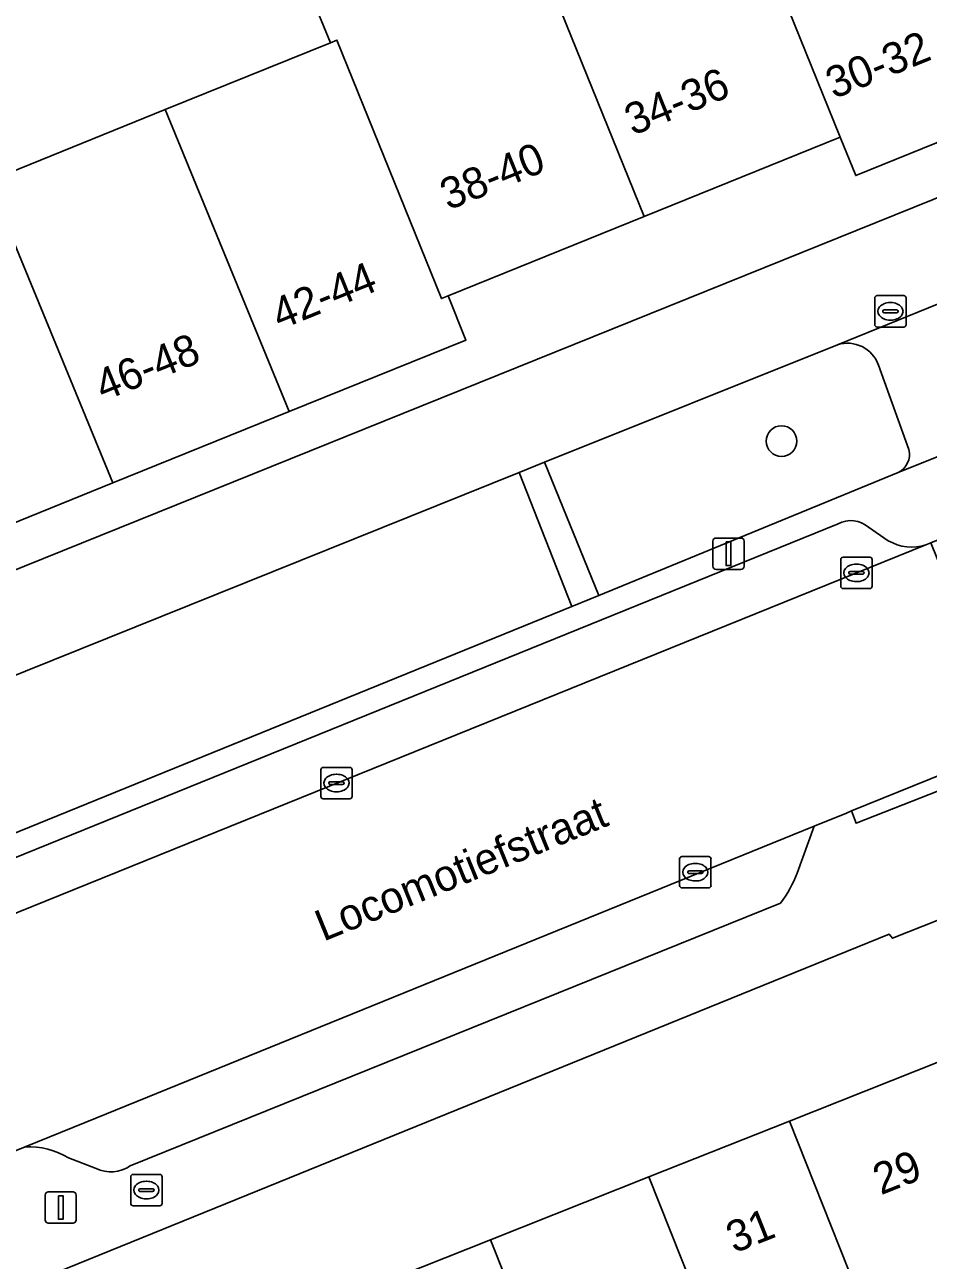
# Model space of a CAD drawing. Extents: x 162989 to 165008, y 383432 to 384338.
# Drawn here: x 163873.96 to 163902.79, y 383958.35 to 383997.76 of the extents above; entities that cross this region are included whole.
import ezdxf

# ---------------------------------------------------------------- set-up
doc = ezdxf.new("R2010")
doc.units = 0
for name, color, linetype in [('IMGEO_Boom', 7, 'Continuous'), ('IMGEO_Brandkraan', 7, 'Continuous'), ('IMGEO_Erf', 7, 'Continuous'), ('IMGEO_Groenvoorziening', 7, 'Continuous'), ('IMGEO_Kolk', 7, 'Continuous'), ('IMGEO_Lichtmast', 7, 'Continuous'), ('IMGEO_Openbare_ruimte_label', 7, 'Continuous'), ('IMGEO_Pand', 7, 'Continuous'), ('IMGEO_Pand_nummerreeks', 7, 'Continuous'), ('IMGEO_Parkeervlak_open', 7, 'Continuous'), ('IMGEO_Rijbaan_lokaal_open', 7, 'Continuous'), ('IMGEO_Rioolput', 7, 'Continuous'), ('IMGEO_Voetpad_open', 7, 'Continuous')]:
    doc.layers.add(name, color=color, linetype=linetype)

msp = doc.modelspace()

# ---------------------------------------------------------------- linework, layer by layer
at = {"layer": 'IMGEO_Boom'}
msp.add_circle((163898.104, 383984.479), 0.489, dxfattribs=at)
at = {"layer": 'IMGEO_Brandkraan'}
for p, q in [((163877.342, 383960.162), (163877.342, 383961.014)), ((163877.417, 383961.088), (163878.269, 383961.088)), ((163878.343, 383961.014), (163878.343, 383960.162)), ((163877.601, 383960.582), (163877.601, 383960.594)), ((163877.644, 383960.631), (163878.042, 383960.631)), ((163877.83, 383960.868), (163877.855, 383960.868)), ((163878.085, 383960.594), (163878.085, 383960.582)), ((163878.039, 383960.545), (163877.641, 383960.545)), ((163877.853, 383960.308), (163877.828, 383960.308)), ((163878.269, 383960.088), (163877.417, 383960.088))]:
    msp.add_line(p, q, dxfattribs=at)
for points in [[(163877.342, 383960.162), (163877.342, 383961.014)], [(163877.417, 383961.088), (163878.269, 383961.088)], [(163878.343, 383961.014), (163878.343, 383960.162)], [(163878.269, 383960.088), (163877.417, 383960.088)]]:
    msp.add_lwpolyline(points, dxfattribs=at)
for centre, radius, start, end in [((163877.419, 383961.012), 0.0765, 91.552, 178.448), ((163877.419, 383961.012), 0.0765, 91.552, 178.448), ((163878.267, 383961.012), 0.0765, 1.552, 88.448), ((163878.267, 383961.012), 0.0765, 1.552, 88.448), ((163877.641, 383960.591), 0.0403, 85.8775, 175.7526), ((163877.638, 383960.581), 0.0366, 178.938, 274.7102), ((163878.042, 383960.588), 0.043, 264.8664, 352.4533), ((163878.046, 383960.593), 0.0386, 1.7309, 96.639), ((163877.419, 383960.164), 0.0765, 181.552, 268.448), ((163877.419, 383960.164), 0.0765, 181.552, 268.448), ((163878.267, 383960.164), 0.0765, 271.552, 358.448), ((163878.267, 383960.164), 0.0765, 271.552, 358.448)]:
    msp.add_arc(centre, radius, start, end, dxfattribs=at)
for centre, major_axis, ratio, start_param, end_param in [((163877.829, 383960.588), (-0.387, 0.002), 0.722429, 4.712389, 7.853982), ((163877.854, 383960.588), (-0.39, 0.002), 0.717154, 1.570796, 4.712389)]:
    msp.add_ellipse(centre, major_axis=major_axis, ratio=ratio, start_param=start_param, end_param=end_param, dxfattribs=at)
at = {"layer": 'IMGEO_Erf'}
for points in [[(163860.657, 383975.132), (163922.286, 384000), (163935.54, 384005.348), (163935.283, 384006.035), (163927.294, 384027.344)], [(163863.146, 383998.341), (163858.852, 383996.609), (163861.551, 383988.223), (163867.173, 383990.498), (163872.805, 383992.776), (163878.436, 383995.055), (163883.712, 383997.189), (163883.071, 383998.773)], [(163906.07, 383995.217), (163900.474, 383992.948), (163899.978, 383994.175), (163893.721, 383991.644), (163887.464, 383989.112), (163888.034, 383987.703), (163882.402, 383985.424), (163876.771, 383983.146), (163871.139, 383980.867), (163865.501, 383978.586), (163865.079, 383979.629), (163857.441, 383976.539)], [(163952.554, 383989.112), (163941.789, 383984.802), (163918.144, 383975.149), (163901.64, 383968.618), (163901.539, 383968.747), (163868.264, 383955.232)], [(163883.709, 383956.971), (163888.821, 383959.002), (163893.876, 383961.01), (163898.355, 383962.789), (163903.224, 383964.723), (163905.069, 383960.077), (163907.655, 383953.567)]]:
    msp.add_lwpolyline(points, dxfattribs=at)
at = {"layer": 'IMGEO_Groenvoorziening'}
for points in [[(163899.886, 383987.554), (163890.546, 383983.807), (163892.281, 383979.552), (163901.827, 383983.48)], [(163902.163, 383984.207), (163901.197, 383986.903)]]:
    msp.add_lwpolyline(points, dxfattribs=at)
msp.add_lwpolyline([(163872.224, 383971.398), (163891.415, 383979.207), (163889.739, 383983.483), (163870.491, 383975.736)], close=True, dxfattribs=at)
for centre, radius, start, end in [((163900.202, 383986.546), 1.057, 19.7624, 107.4226), ((163901.563, 383984.043), 0.622, 295.134, 15.2557)]:
    msp.add_arc(centre, radius, start, end, dxfattribs=at)
at = {"layer": 'IMGEO_Kolk'}
for p, q in [((163899.994, 383979.85), (163899.994, 383980.702)), ((163900.069, 383980.776), (163900.921, 383980.776)), ((163900.995, 383980.702), (163900.995, 383979.85)), ((163900.253, 383980.27), (163900.253, 383980.282)), ((163900.296, 383980.319), (163900.694, 383980.319)), ((163900.482, 383980.556), (163900.507, 383980.556)), ((163900.737, 383980.282), (163900.737, 383980.27)), ((163900.691, 383980.233), (163900.293, 383980.233)), ((163900.505, 383979.996), (163900.48, 383979.996)), ((163900.921, 383979.776), (163900.069, 383979.776)), ((163883.406, 383973.146), (163883.406, 383973.998)), ((163883.481, 383974.072), (163884.333, 383974.072)), ((163884.407, 383973.998), (163884.407, 383973.146)), ((163883.665, 383973.566), (163883.665, 383973.578)), ((163883.708, 383973.615), (163884.106, 383973.615)), ((163883.894, 383973.852), (163883.919, 383973.852)), ((163884.149, 383973.578), (163884.149, 383973.566)), ((163884.103, 383973.529), (163883.705, 383973.529)), ((163883.917, 383973.292), (163883.892, 383973.292)), ((163884.333, 383973.072), (163883.481, 383973.072)), ((163894.928, 383971.227), (163895.78, 383971.227)), ((163894.853, 383970.301), (163894.853, 383971.153)), ((163895.341, 383971.007), (163895.366, 383971.007)), ((163895.854, 383971.153), (163895.854, 383970.301)), ((163895.112, 383970.721), (163895.112, 383970.733)), ((163895.55, 383970.684), (163895.152, 383970.684)), ((163895.155, 383970.77), (163895.553, 383970.77)), ((163895.364, 383970.447), (163895.339, 383970.447)), ((163895.596, 383970.733), (163895.596, 383970.721)), ((163895.78, 383970.227), (163894.928, 383970.227))]:
    msp.add_line(p, q, dxfattribs=at)
for points in [[(163899.994, 383979.85), (163899.994, 383980.702)], [(163900.069, 383980.776), (163900.921, 383980.776)], [(163900.995, 383980.702), (163900.995, 383979.85)], [(163900.921, 383979.776), (163900.069, 383979.776)], [(163883.406, 383973.146), (163883.406, 383973.998)], [(163883.481, 383974.072), (163884.333, 383974.072)], [(163884.407, 383973.998), (163884.407, 383973.146)], [(163884.333, 383973.072), (163883.481, 383973.072)], [(163894.928, 383971.227), (163895.78, 383971.227)], [(163894.853, 383970.301), (163894.853, 383971.153)], [(163895.854, 383971.153), (163895.854, 383970.301)], [(163895.78, 383970.227), (163894.928, 383970.227)]]:
    msp.add_lwpolyline(points, dxfattribs=at)
for centre, radius, start, end in [((163900.071, 383980.7), 0.0765, 91.552, 178.448), ((163900.071, 383980.7), 0.0765, 91.552, 178.448), ((163900.919, 383980.7), 0.0765, 1.552, 88.448), ((163900.919, 383980.7), 0.0765, 1.552, 88.448), ((163900.293, 383980.279), 0.0403, 85.8775, 175.7526), ((163900.29, 383980.269), 0.0366, 178.938, 274.7102), ((163900.694, 383980.276), 0.043, 264.8664, 352.4533), ((163900.698, 383980.281), 0.0386, 1.7309, 96.639), ((163900.071, 383979.852), 0.0765, 181.552, 268.448), ((163900.071, 383979.852), 0.0765, 181.552, 268.448), ((163900.919, 383979.852), 0.0765, 271.552, 358.448), ((163900.919, 383979.852), 0.0765, 271.552, 358.448), ((163883.483, 383973.996), 0.0765, 91.552, 178.448), ((163883.483, 383973.996), 0.0765, 91.552, 178.448), ((163884.331, 383973.996), 0.0765, 1.552, 88.448), ((163884.331, 383973.996), 0.0765, 1.552, 88.448), ((163883.705, 383973.575), 0.0403, 85.8775, 175.7526), ((163883.702, 383973.565), 0.0366, 178.938, 274.7102), ((163884.106, 383973.572), 0.043, 264.8664, 352.4533), ((163884.11, 383973.577), 0.0386, 1.7309, 96.639), ((163883.483, 383973.148), 0.0765, 181.552, 268.448), ((163883.483, 383973.148), 0.0765, 181.552, 268.448), ((163884.331, 383973.148), 0.0765, 271.552, 358.448), ((163884.331, 383973.148), 0.0765, 271.552, 358.448), ((163894.93, 383971.151), 0.0765, 91.552, 178.448), ((163894.93, 383971.151), 0.0765, 91.552, 178.448), ((163895.778, 383971.151), 0.0765, 1.552, 88.448), ((163895.778, 383971.151), 0.0765, 1.552, 88.448), ((163895.152, 383970.73), 0.0403, 85.8775, 175.7526), ((163895.149, 383970.72), 0.0366, 178.938, 274.7102), ((163895.553, 383970.727), 0.043, 264.8664, 352.4533), ((163895.557, 383970.732), 0.0386, 1.7309, 96.639), ((163894.93, 383970.303), 0.0765, 181.552, 268.448), ((163894.93, 383970.303), 0.0765, 181.552, 268.448), ((163895.778, 383970.303), 0.0765, 271.552, 358.448), ((163895.778, 383970.303), 0.0765, 271.552, 358.448)]:
    msp.add_arc(centre, radius, start, end, dxfattribs=at)
for centre, major_axis, ratio, start_param, end_param in [((163900.481, 383980.276), (-0.387, 0.002), 0.722429, 4.712389, 7.853982), ((163900.506, 383980.276), (-0.39, 0.002), 0.717154, 1.570796, 4.712389), ((163883.893, 383973.572), (-0.387, 0.002), 0.722429, 4.712389, 7.853982), ((163883.918, 383973.572), (-0.39, 0.002), 0.717154, 1.570796, 4.712389), ((163895.34, 383970.727), (-0.387, 0.002), 0.722429, 4.712389, 7.853982), ((163895.365, 383970.727), (-0.39, 0.002), 0.717154, 1.570796, 4.712389)]:
    msp.add_ellipse(centre, major_axis=major_axis, ratio=ratio, start_param=start_param, end_param=end_param, dxfattribs=at)
at = {"layer": 'IMGEO_Lichtmast'}
for p, q in [((163895.917, 383980.486), (163895.917, 383981.286)), ((163895.917, 383981.286), (163895.917, 383980.486)), ((163896.017, 383981.386), (163896.807, 383981.386)), ((163896.807, 383981.386), (163896.017, 383981.386)), ((163896.907, 383981.286), (163896.907, 383980.486)), ((163896.907, 383980.486), (163896.907, 383981.286)), ((163896.807, 383980.386), (163896.017, 383980.386)), ((163896.017, 383980.386), (163896.807, 383980.386)), ((163874.613, 383959.63), (163874.613, 383960.43)), ((163874.613, 383960.43), (163874.613, 383959.63)), ((163874.713, 383960.53), (163875.503, 383960.53)), ((163875.503, 383960.53), (163874.713, 383960.53)), ((163875.603, 383960.43), (163875.603, 383959.63)), ((163875.603, 383959.63), (163875.603, 383960.43)), ((163875.503, 383959.53), (163874.713, 383959.53)), ((163874.713, 383959.53), (163875.503, 383959.53))]:
    msp.add_line(p, q, dxfattribs=at)
for points in [[(163896.337, 383981.261), (163896.487, 383981.261), (163896.487, 383980.511), (163896.337, 383980.511), (163896.337, 383981.261)], [(163875.033, 383960.405), (163875.183, 383960.405), (163875.183, 383959.655), (163875.033, 383959.655), (163875.033, 383960.405)]]:
    msp.add_lwpolyline(points, dxfattribs=at)
for centre, start, end in [((163896.017, 383981.286), 90, 180), ((163896.017, 383981.286), 90, 180), ((163896.807, 383981.286), 0, 90), ((163896.807, 383981.286), 360, 90), ((163896.017, 383980.486), 180, 270), ((163896.017, 383980.486), 180, 270), ((163896.807, 383980.486), 270, 0), ((163896.807, 383980.486), 270, 0), ((163874.713, 383960.43), 90, 180), ((163874.713, 383960.43), 90, 180), ((163875.503, 383960.43), 0, 90), ((163875.503, 383960.43), 360, 90), ((163874.713, 383959.63), 180, 270), ((163874.713, 383959.63), 180, 270), ((163875.503, 383959.63), 270, 0), ((163875.503, 383959.63), 270, 0)]:
    msp.add_arc(centre, 0.1, start, end, dxfattribs=at)
at = {"layer": 'IMGEO_Pand'}
for points in [[(163902.084, 384005.049), (163896.496, 384002.78), (163899.978, 383994.175), (163900.474, 383992.948), (163906.07, 383995.217)], [(163893.721, 383991.644), (163899.978, 383994.175), (163896.496, 384002.78), (163894.969, 384002.16), (163894.477, 384003.373), (163889.748, 384001.466)], [(163889.748, 384001.466), (163886.113, 384000), (163883.488, 383998.941), (163883.071, 383998.773), (163883.712, 383997.189), (163883.92, 383997.273), (163887.255, 383989.028), (163887.464, 383989.112), (163893.721, 383991.644)], [(163883.92, 383997.273), (163883.712, 383997.189), (163878.436, 383995.055), (163882.402, 383985.424), (163888.034, 383987.703), (163887.464, 383989.112), (163887.255, 383989.028)], [(163878.436, 383995.055), (163872.805, 383992.776), (163876.771, 383983.146), (163882.402, 383985.424)], [(163867.173, 383990.498), (163871.139, 383980.867), (163876.771, 383983.146), (163872.805, 383992.776)], [(163898.355, 383962.789), (163901.306, 383955.36), (163903.74, 383956.327), (163905.222, 383952.6), (163907.655, 383953.567), (163905.069, 383960.077), (163903.224, 383964.723)], [(163898.308, 383949.855), (163900.509, 383950.729), (163899.029, 383954.455), (163901.306, 383955.36), (163898.355, 383962.789), (163893.876, 383961.01)], [(163898.308, 383949.855), (163893.876, 383961.01), (163888.821, 383959.002), (163891.772, 383951.573), (163894.522, 383952.665), (163896.002, 383948.939)], [(163888.821, 383959.002), (163883.709, 383956.971), (163888.141, 383945.816), (163890.343, 383946.69), (163892.926, 383947.715), (163891.446, 383951.444), (163891.772, 383951.573)]]:
    msp.add_lwpolyline(points, close=True, dxfattribs=at)
at = {"layer": 'IMGEO_Parkeervlak_open'}
for points in [[(163899.909, 383981.843), (163868.281, 383969.012)], [(163901.511, 383981.303), (163900.874, 383981.733)], [(163866.484, 383966.516), (163902.71, 383981.172)], [(163898.6, 383970.701), (163899.148, 383972.197), (163875.885, 383962.746), (163873.978, 383961.971)], [(163877.329, 383961.358), (163898.069, 383969.743)], [(163875.36, 383961.618), (163876.235, 383961.274)]]:
    msp.add_lwpolyline(points, dxfattribs=at)
for centre, radius, start, end in [((163900.312, 383981.093), 0.852, 48.7346, 118.2593), ((163902.255, 383982.56), 1.461, 239.3791, 288.1504), ((163895.405, 383971.846), 3.394, 321.7152, 340.2873), ((163874.072, 383959.458), 2.515, 59.198, 92.145), ((163876.707, 383962.293), 1.123, 245.1465, 303.6349)]:
    msp.add_arc(centre, radius, start, end, dxfattribs=at)
at = {"layer": 'IMGEO_Rijbaan_lokaal_open'}
for points in [[(163899.148, 383972.197), (163900.176, 383972.615), (163900.336, 383972.68), (163903.835, 383974.102), (163903.966, 383974.155), (163905.486, 383974.773), (163902.862, 383981.233), (163902.71, 383981.172), (163866.484, 383966.516), (163866.224, 383966.406), (163866.079, 383966.355), (163868.869, 383959.329)], [(163870.987, 383960.755), (163873.978, 383961.971), (163875.885, 383962.746), (163899.148, 383972.197)]]:
    msp.add_lwpolyline(points, dxfattribs=at)
at = {"layer": 'IMGEO_Rioolput'}
for p, q in [((163901.078, 383988.193), (163901.078, 383989.045)), ((163901.153, 383989.119), (163902.005, 383989.119)), ((163902.079, 383989.045), (163902.079, 383988.193)), ((163901.337, 383988.613), (163901.337, 383988.625)), ((163901.775, 383988.576), (163901.377, 383988.576)), ((163901.38, 383988.662), (163901.778, 383988.662)), ((163901.566, 383988.899), (163901.591, 383988.899)), ((163901.821, 383988.625), (163901.821, 383988.613)), ((163901.589, 383988.339), (163901.564, 383988.339)), ((163902.005, 383988.119), (163901.153, 383988.119))]:
    msp.add_line(p, q, dxfattribs=at)
for points in [[(163901.078, 383988.193), (163901.078, 383989.045)], [(163901.153, 383989.119), (163902.005, 383989.119)], [(163902.079, 383989.045), (163902.079, 383988.193)], [(163902.005, 383988.119), (163901.153, 383988.119)]]:
    msp.add_lwpolyline(points, dxfattribs=at)
for centre, radius, start, end in [((163901.155, 383989.043), 0.0765, 91.552, 178.448), ((163901.155, 383989.043), 0.0765, 91.552, 178.448), ((163902.003, 383989.043), 0.0765, 1.552, 88.448), ((163902.003, 383989.043), 0.0765, 1.552, 88.448), ((163901.377, 383988.622), 0.0403, 85.8775, 175.7526), ((163901.374, 383988.612), 0.0366, 178.938, 274.7102), ((163901.778, 383988.619), 0.043, 264.8664, 352.4533), ((163901.782, 383988.624), 0.0386, 1.7309, 96.639), ((163901.155, 383988.195), 0.0765, 181.552, 268.448), ((163901.155, 383988.195), 0.0765, 181.552, 268.448), ((163902.003, 383988.195), 0.0765, 271.552, 358.448), ((163902.003, 383988.195), 0.0765, 271.552, 358.448)]:
    msp.add_arc(centre, radius, start, end, dxfattribs=at)
for centre, major_axis, ratio, start_param, end_param in [((163901.565, 383988.619), (-0.387, 0.002), 0.722429, 4.712389, 7.853982), ((163901.59, 383988.619), (-0.39, 0.002), 0.717154, 1.570796, 4.712389)]:
    msp.add_ellipse(centre, major_axis=major_axis, ratio=ratio, start_param=start_param, end_param=end_param, dxfattribs=at)
at = {"layer": 'IMGEO_Voetpad_open'}
for points in [[(163939.919, 384003.04), (163938.767, 384006.115), (163937.352, 384005.559), (163937.132, 384006.117), (163938.547, 384006.674), (163938.328, 384007.232), (163936.28, 384006.427), (163935.283, 384006.035), (163935.54, 384005.348), (163922.286, 384000), (163860.657, 383975.132)], [(163861.708, 383972.246), (163869.582, 383975.37), (163870.491, 383975.736), (163889.739, 383983.483), (163890.546, 383983.807), (163899.886, 383987.554), (163904.39, 383989.379), (163912.57, 383992.705), (163913.546, 383993.102), (163929.686, 383999.636), (163930.666, 383999.968), (163938.946, 384003.453)], [(163943.911, 383999.998), (163944.428, 384001.499), (163941.121, 384000), (163940.918, 383999.359), (163932.321, 383995.796), (163931.364, 383995.406), (163915.242, 383988.827), (163914.265, 383988.432), (163905.625, 383984.998), (163901.827, 383983.48), (163892.281, 383979.552), (163891.415, 383979.207), (163872.224, 383971.398), (163871.367, 383971.048), (163865.192, 383968.522), (163866.079, 383966.355), (163866.224, 383966.406), (163866.484, 383966.516)], [(163867.106, 383954.34), (163868.264, 383955.232), (163901.539, 383968.747), (163901.64, 383968.618), (163918.144, 383975.149), (163941.789, 383984.802), (163952.554, 383989.112), (163962.348, 383993.055), (163980.091, 384000)], [(163904.39, 383989.379), (163899.886, 383987.554)], [(163901.197, 383986.903), (163902.163, 383984.207)], [(163901.827, 383983.48), (163905.625, 383984.998)], [(163902.71, 383981.172), (163902.862, 383981.233), (163905.412, 383982.265), (163906.416, 383982.671)], [(163868.281, 383969.012), (163899.909, 383981.843)], [(163900.874, 383981.733), (163901.511, 383981.303)], [(163903.966, 383974.155), (163903.835, 383974.102), (163904, 383973.674), (163900.485, 383972.288), (163900.336, 383972.68), (163900.176, 383972.615), (163899.148, 383972.197), (163898.6, 383970.701)], [(163898.069, 383969.743), (163877.329, 383961.358)], [(163873.978, 383961.971), (163870.987, 383960.755)], [(163876.235, 383961.274), (163875.36, 383961.618)]]:
    msp.add_lwpolyline(points, dxfattribs=at)
for points in [[(163890.546, 383983.807), (163889.739, 383983.483), (163891.415, 383979.207), (163892.281, 383979.552)], [(163903.835, 383974.102), (163900.336, 383972.68), (163900.485, 383972.288), (163904, 383973.674)]]:
    msp.add_lwpolyline(points, close=True, dxfattribs=at)
for centre, radius, start, end in [((163900.202, 383986.546), 1.057, 19.7624, 107.4226), ((163901.563, 383984.043), 0.622, 295.134, 15.2557), ((163900.312, 383981.093), 0.852, 48.7346, 118.2593), ((163902.255, 383982.56), 1.461, 239.3791, 288.1504), ((163895.405, 383971.846), 3.394, 321.7152, 340.2873), ((163874.072, 383959.458), 2.515, 59.198, 92.145), ((163876.707, 383962.293), 1.123, 245.1465, 303.6349)]:
    msp.add_arc(centre, radius, start, end, dxfattribs=at)

# ---------------------------------------------------------------- texts
at = {"layer": 'IMGEO_Openbare_ruimte_label'}
msp.add_text('Locomotiefstraat', height=1, rotation=22.1526, dxfattribs=at).set_placement((163883.488, 383968.509))
at = {"layer": 'IMGEO_Pand_nummerreeks'}
for s, rotation, p in [('30-32', 22.071, (163899.775, 383995.384)), ('34-36', 22.0276, (163893.359, 383994.216)), ('38-40', 22.0302, (163887.473, 383991.833)), ('42-44', 22.0302, (163882.098, 383988.019)), ('46-48', 22.0286, (163876.466, 383985.741)), ('29', 21.6641, (163901.274, 383960.419)), ('31', 21.6641, (163896.594, 383958.561))]:
    msp.add_text(s, height=1, rotation=rotation, dxfattribs=at).set_placement(p)

doc.saveas('drawing.dxf')
